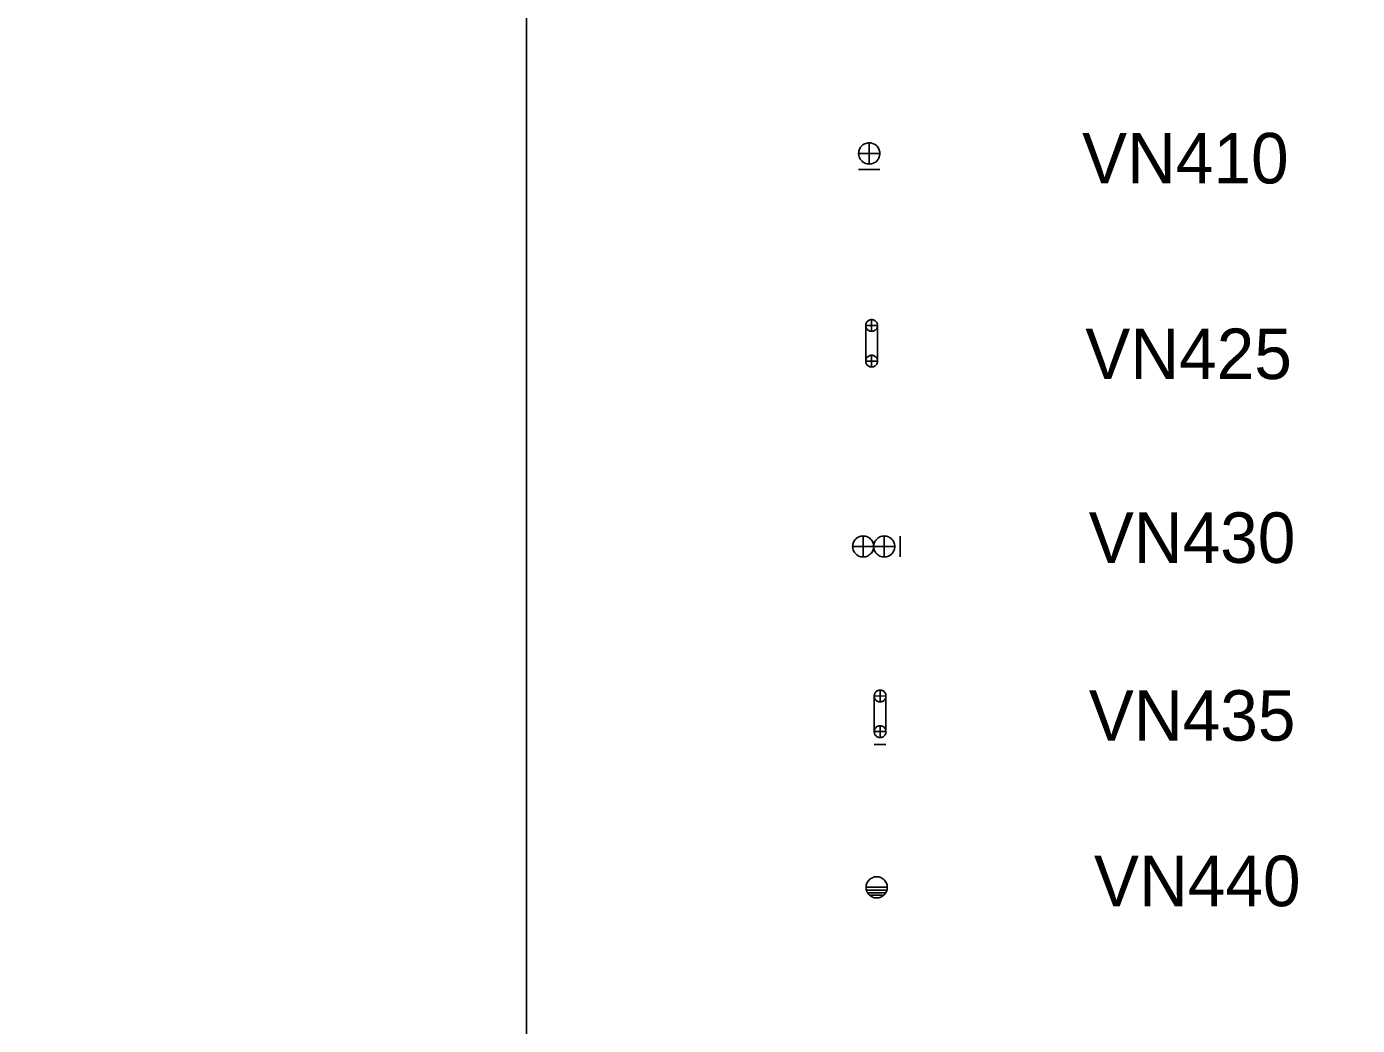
# Model space of a CAD drawing. Extents: x -592825 to -592404, y -1153473 to -1153230.
# Drawn here: x -592615.49 to -592575.99, y -1153381.85 to -1153352.19 of the extents above; entities that cross this region are included whole.
import ezdxf

# ---------------------------------------------------------------- set-up
doc = ezdxf.new("R2010")
doc.units = 0
doc.layers.add('Vrstva 45', color=7, linetype='Continuous')
doc.layers.add('Vrstva 63', color=7, linetype='Continuous')

msp = doc.modelspace()

# ---------------------------------------------------------------- linework, layer by layer
at = {"layer": 'Vrstva 45'}
for points in [[(-592590.165, -1153355.955), (-592590.167, -1153355.922), (-592590.171, -1153355.89), (-592590.18, -1153355.858), (-592590.192, -1153355.826), (-592590.207, -1153355.798), (-592590.225, -1153355.77), (-592590.245, -1153355.744), (-592590.269, -1153355.721), (-592590.295, -1153355.7), (-592590.323, -1153355.682), (-592590.351, -1153355.667), (-592590.383, -1153355.656), (-592590.415, -1153355.646), (-592590.447, -1153355.642), (-592590.48, -1153355.64), (-592590.513, -1153355.642), (-592590.545, -1153355.646), (-592590.577, -1153355.656), (-592590.608, -1153355.668), (-592590.637, -1153355.682), (-592590.665, -1153355.7), (-592590.691, -1153355.72), (-592590.714, -1153355.744), (-592590.735, -1153355.77), (-592590.753, -1153355.798), (-592590.767, -1153355.826), (-592590.779, -1153355.858), (-592590.788, -1153355.89), (-592590.793, -1153355.922), (-592590.795, -1153355.956), (-592590.793, -1153355.988), (-592590.788, -1153356.02), (-592590.78, -1153356.052), (-592590.767, -1153356.083), (-592590.753, -1153356.112), (-592590.735, -1153356.14), (-592590.714, -1153356.166), (-592590.691, -1153356.189), (-592590.665, -1153356.21), (-592590.637, -1153356.228), (-592590.608, -1153356.243), (-592590.577, -1153356.254), (-592590.545, -1153356.263), (-592590.513, -1153356.268), (-592590.48, -1153356.27), (-592590.447, -1153356.268), (-592590.415, -1153356.264), (-592590.383, -1153356.254), (-592590.351, -1153356.242), (-592590.323, -1153356.228), (-592590.295, -1153356.21), (-592590.269, -1153356.19), (-592590.245, -1153356.166), (-592590.225, -1153356.14), (-592590.207, -1153356.112), (-592590.192, -1153356.083), (-592590.18, -1153356.052), (-592590.171, -1153356.02), (-592590.167, -1153355.988), (-592590.165, -1153355.955)], [(-592590.481, -1153355.639), (-592590.481, -1153356.269)], [(-592590.797, -1153355.954), (-592590.166, -1153355.954)], [(-592590.796, -1153356.432), (-592590.166, -1153356.432)], [(-592590.235, -1153361.064), (-592590.235, -1153361.046), (-592590.238, -1153361.028), (-592590.243, -1153361.01), (-592590.249, -1153360.993), (-592590.257, -1153360.976), (-592590.267, -1153360.962), (-592590.279, -1153360.947), (-592590.292, -1153360.934), (-592590.306, -1153360.923), (-592590.321, -1153360.912), (-592590.337, -1153360.904), (-592590.355, -1153360.898), (-592590.373, -1153360.893), (-592590.391, -1153360.89), (-592590.409, -1153360.89), (-592590.427, -1153360.89), (-592590.445, -1153360.893), (-592590.463, -1153360.898), (-592590.479, -1153360.904), (-592590.496, -1153360.912), (-592590.511, -1153360.923), (-592590.525, -1153360.934), (-592590.538, -1153360.947), (-592590.549, -1153360.962), (-592590.56, -1153360.976), (-592590.568, -1153360.993), (-592590.575, -1153361.01), (-592590.579, -1153361.028), (-592590.582, -1153361.046), (-592590.583, -1153361.064), (-592590.582, -1153361.082), (-592590.579, -1153361.1), (-592590.575, -1153361.118), (-592590.568, -1153361.135), (-592590.56, -1153361.151), (-592590.55, -1153361.166), (-592590.539, -1153361.18), (-592590.525, -1153361.194), (-592590.511, -1153361.206), (-592590.496, -1153361.215), (-592590.479, -1153361.224), (-592590.463, -1153361.23), (-592590.445, -1153361.234), (-592590.427, -1153361.238), (-592590.409, -1153361.238), (-592590.391, -1153361.238), (-592590.373, -1153361.234), (-592590.355, -1153361.23), (-592590.337, -1153361.224), (-592590.321, -1153361.215), (-592590.306, -1153361.205), (-592590.292, -1153361.194), (-592590.279, -1153361.18), (-592590.267, -1153361.166), (-592590.257, -1153361.151), (-592590.249, -1153361.135), (-592590.243, -1153361.118), (-592590.238, -1153361.1), (-592590.235, -1153361.082), (-592590.235, -1153361.064)], [(-592590.235, -1153361.064), (-592590.583, -1153361.064)], [(-592590.583, -1153361.064), (-592590.583, -1153362.122)], [(-592590.409, -1153360.89), (-592590.409, -1153361.238)], [(-592590.235, -1153361.064), (-592590.234, -1153362.122)], [(-592590.234, -1153362.122), (-592590.235, -1153362.104), (-592590.238, -1153362.086), (-592590.243, -1153362.068), (-592590.249, -1153362.051), (-592590.257, -1153362.035), (-592590.267, -1153362.02), (-592590.279, -1153362.006), (-592590.292, -1153361.992), (-592590.306, -1153361.981), (-592590.321, -1153361.971), (-592590.337, -1153361.962), (-592590.355, -1153361.956), (-592590.373, -1153361.952), (-592590.391, -1153361.949), (-592590.409, -1153361.948), (-592590.427, -1153361.949), (-592590.445, -1153361.952), (-592590.463, -1153361.956), (-592590.48, -1153361.963), (-592590.496, -1153361.971), (-592590.511, -1153361.981), (-592590.525, -1153361.992), (-592590.539, -1153362.006), (-592590.549, -1153362.02), (-592590.56, -1153362.035), (-592590.568, -1153362.051), (-592590.575, -1153362.068), (-592590.579, -1153362.086), (-592590.582, -1153362.104), (-592590.583, -1153362.122), (-592590.582, -1153362.14), (-592590.579, -1153362.158), (-592590.575, -1153362.176), (-592590.568, -1153362.193), (-592590.56, -1153362.21), (-592590.55, -1153362.224), (-592590.538, -1153362.239), (-592590.525, -1153362.252), (-592590.511, -1153362.264), (-592590.496, -1153362.273), (-592590.48, -1153362.282), (-592590.463, -1153362.288), (-592590.445, -1153362.293), (-592590.427, -1153362.296), (-592590.409, -1153362.296), (-592590.391, -1153362.296), (-592590.373, -1153362.293), (-592590.355, -1153362.288), (-592590.337, -1153362.282), (-592590.321, -1153362.273), (-592590.306, -1153362.264), (-592590.291, -1153362.252), (-592590.279, -1153362.239), (-592590.267, -1153362.225), (-592590.257, -1153362.21), (-592590.249, -1153362.194), (-592590.243, -1153362.176), (-592590.238, -1153362.158), (-592590.235, -1153362.14), (-592590.234, -1153362.122)], [(-592590.234, -1153362.122), (-592590.583, -1153362.122)], [(-592590.409, -1153361.948), (-592590.409, -1153362.296)], [(-592590.347, -1153367.628), (-592590.349, -1153367.595), (-592590.354, -1153367.562), (-592590.363, -1153367.531), (-592590.375, -1153367.501), (-592590.389, -1153367.472), (-592590.407, -1153367.444), (-592590.428, -1153367.418), (-592590.451, -1153367.396), (-592590.476, -1153367.375), (-592590.503, -1153367.357), (-592590.533, -1153367.342), (-592590.563, -1153367.33), (-592590.595, -1153367.322), (-592590.627, -1153367.318), (-592590.659, -1153367.315), (-592590.693, -1153367.318), (-592590.725, -1153367.322), (-592590.757, -1153367.331), (-592590.787, -1153367.342), (-592590.816, -1153367.358), (-592590.843, -1153367.375), (-592590.869, -1153367.396), (-592590.892, -1153367.419), (-592590.913, -1153367.444), (-592590.93, -1153367.472), (-592590.945, -1153367.5), (-592590.957, -1153367.531), (-592590.965, -1153367.563), (-592590.971, -1153367.595), (-592590.973, -1153367.628), (-592590.971, -1153367.66), (-592590.965, -1153367.692), (-592590.957, -1153367.724), (-592590.945, -1153367.756), (-592590.93, -1153367.784), (-592590.913, -1153367.811), (-592590.892, -1153367.836), (-592590.869, -1153367.86), (-592590.843, -1153367.88), (-592590.815, -1153367.898), (-592590.787, -1153367.913), (-592590.757, -1153367.924), (-592590.725, -1153367.934), (-592590.693, -1153367.938), (-592590.659, -1153367.94), (-592590.627, -1153367.939), (-592590.595, -1153367.934), (-592590.563, -1153367.925), (-592590.533, -1153367.913), (-592590.503, -1153367.898), (-592590.477, -1153367.88), (-592590.451, -1153367.86), (-592590.428, -1153367.837), (-592590.407, -1153367.812), (-592590.389, -1153367.784), (-592590.374, -1153367.755), (-592590.363, -1153367.724), (-592590.354, -1153367.693), (-592590.349, -1153367.661), (-592590.347, -1153367.628)], [(-592590.657, -1153367.318), (-592590.657, -1153367.938)], [(-592589.722, -1153367.628), (-592589.724, -1153367.595), (-592589.729, -1153367.563), (-592589.738, -1153367.531), (-592589.749, -1153367.501), (-592589.764, -1153367.472), (-592589.782, -1153367.444), (-592589.803, -1153367.418), (-592589.825, -1153367.396), (-592589.851, -1153367.376), (-592589.879, -1153367.358), (-592589.908, -1153367.342), (-592589.938, -1153367.33), (-592589.97, -1153367.322), (-592590.002, -1153367.318), (-592590.035, -1153367.315), (-592590.067, -1153367.318), (-592590.099, -1153367.322), (-592590.131, -1153367.331), (-592590.163, -1153367.342), (-592590.191, -1153367.358), (-592590.218, -1153367.375), (-592590.243, -1153367.396), (-592590.267, -1153367.419), (-592590.287, -1153367.444), (-592590.305, -1153367.472), (-592590.321, -1153367.501), (-592590.331, -1153367.532), (-592590.341, -1153367.562), (-592590.345, -1153367.595), (-592590.347, -1153367.628), (-592590.346, -1153367.661), (-592590.341, -1153367.693), (-592590.331, -1153367.724), (-592590.32, -1153367.756), (-592590.305, -1153367.784), (-592590.288, -1153367.812), (-592590.267, -1153367.836), (-592590.244, -1153367.86), (-592590.218, -1153367.88), (-592590.191, -1153367.898), (-592590.161, -1153367.914), (-592590.131, -1153367.924), (-592590.1, -1153367.934), (-592590.067, -1153367.938), (-592590.035, -1153367.94), (-592590.002, -1153367.938), (-592589.969, -1153367.934), (-592589.938, -1153367.925), (-592589.908, -1153367.914), (-592589.879, -1153367.898), (-592589.851, -1153367.881), (-592589.825, -1153367.86), (-592589.803, -1153367.837), (-592589.782, -1153367.812), (-592589.765, -1153367.784), (-592589.749, -1153367.755), (-592589.737, -1153367.724), (-592589.729, -1153367.693), (-592589.724, -1153367.661), (-592589.722, -1153367.628)], [(-592590.037, -1153367.318), (-592590.037, -1153367.938)], [(-592589.565, -1153367.318), (-592589.565, -1153367.938)], [(-592590.973, -1153367.628), (-592589.722, -1153367.628)], [(-592589.983, -1153372.069), (-592589.983, -1153372.05), (-592589.987, -1153372.032), (-592589.991, -1153372.015), (-592589.997, -1153371.998), (-592590.006, -1153371.982), (-592590.016, -1153371.966), (-592590.027, -1153371.952), (-592590.041, -1153371.939), (-592590.055, -1153371.928), (-592590.07, -1153371.918), (-592590.086, -1153371.909), (-592590.103, -1153371.902), (-592590.121, -1153371.898), (-592590.139, -1153371.896), (-592590.157, -1153371.894), (-592590.175, -1153371.895), (-592590.193, -1153371.898), (-592590.211, -1153371.903), (-592590.228, -1153371.91), (-592590.245, -1153371.918), (-592590.26, -1153371.928), (-592590.274, -1153371.939), (-592590.287, -1153371.952), (-592590.299, -1153371.966), (-592590.308, -1153371.982), (-592590.317, -1153371.998), (-592590.323, -1153372.015), (-592590.328, -1153372.032), (-592590.331, -1153372.05), (-592590.331, -1153372.068), (-592590.331, -1153372.087), (-592590.328, -1153372.105), (-592590.323, -1153372.123), (-592590.317, -1153372.14), (-592590.309, -1153372.156), (-592590.298, -1153372.171), (-592590.287, -1153372.186), (-592590.274, -1153372.198), (-592590.26, -1153372.21), (-592590.245, -1153372.22), (-592590.228, -1153372.228), (-592590.211, -1153372.234), (-592590.193, -1153372.24), (-592590.175, -1153372.242), (-592590.157, -1153372.243), (-592590.139, -1153372.242), (-592590.121, -1153372.24), (-592590.103, -1153372.234), (-592590.086, -1153372.228), (-592590.07, -1153372.22), (-592590.055, -1153372.21), (-592590.041, -1153372.198), (-592590.027, -1153372.186), (-592590.016, -1153372.171), (-592590.006, -1153372.156), (-592589.997, -1153372.14), (-592589.991, -1153372.122), (-592589.987, -1153372.105), (-592589.983, -1153372.087), (-592589.983, -1153372.069)], [(-592589.983, -1153372.069), (-592590.331, -1153372.068)], [(-592590.331, -1153372.068), (-592590.331, -1153373.127)], [(-592590.157, -1153371.894), (-592590.157, -1153372.243)], [(-592589.983, -1153372.069), (-592589.983, -1153373.127)], [(-592589.983, -1153373.127), (-592589.983, -1153373.108), (-592589.987, -1153373.091), (-592589.991, -1153373.074), (-592589.997, -1153373.056), (-592590.006, -1153373.04), (-592590.016, -1153373.024), (-592590.027, -1153373.01), (-592590.041, -1153372.997), (-592590.055, -1153372.986), (-592590.069, -1153372.976), (-592590.086, -1153372.968), (-592590.103, -1153372.961), (-592590.121, -1153372.956), (-592590.139, -1153372.954), (-592590.157, -1153372.952), (-592590.175, -1153372.954), (-592590.193, -1153372.956), (-592590.211, -1153372.961), (-592590.228, -1153372.968), (-592590.245, -1153372.976), (-592590.26, -1153372.986), (-592590.274, -1153372.997), (-592590.287, -1153373.01), (-592590.299, -1153373.024), (-592590.309, -1153373.04), (-592590.317, -1153373.056), (-592590.323, -1153373.074), (-592590.327, -1153373.09), (-592590.331, -1153373.108), (-592590.331, -1153373.127), (-592590.331, -1153373.145), (-592590.328, -1153373.164), (-592590.323, -1153373.181), (-592590.317, -1153373.198), (-592590.309, -1153373.214), (-592590.299, -1153373.23), (-592590.287, -1153373.244), (-592590.274, -1153373.256), (-592590.26, -1153373.268), (-592590.245, -1153373.278), (-592590.228, -1153373.286), (-592590.211, -1153373.293), (-592590.193, -1153373.298), (-592590.175, -1153373.3), (-592590.157, -1153373.302), (-592590.139, -1153373.3), (-592590.121, -1153373.298), (-592590.103, -1153373.293), (-592590.086, -1153373.286), (-592590.069, -1153373.278), (-592590.055, -1153373.268), (-592590.041, -1153373.256), (-592590.027, -1153373.244), (-592590.016, -1153373.23), (-592590.006, -1153373.214), (-592589.997, -1153373.198), (-592589.991, -1153373.181), (-592589.987, -1153373.163), (-592589.983, -1153373.145), (-592589.983, -1153373.127)], [(-592589.983, -1153373.127), (-592590.331, -1153373.127)], [(-592590.157, -1153372.952), (-592590.157, -1153373.302)], [(-592590.338, -1153373.504), (-592589.983, -1153373.504)], [(-592589.945, -1153377.751), (-592589.946, -1153377.718), (-592589.951, -1153377.686), (-592589.959, -1153377.654), (-592589.971, -1153377.623), (-592589.987, -1153377.593), (-592590.005, -1153377.566), (-592590.025, -1153377.54), (-592590.049, -1153377.517), (-592590.074, -1153377.496), (-592590.101, -1153377.478), (-592590.131, -1153377.463), (-592590.162, -1153377.451), (-592590.193, -1153377.442), (-592590.226, -1153377.438), (-592590.259, -1153377.436), (-592590.292, -1153377.438), (-592590.325, -1153377.443), (-592590.357, -1153377.451), (-592590.387, -1153377.464), (-592590.417, -1153377.478), (-592590.445, -1153377.496), (-592590.47, -1153377.517), (-592590.493, -1153377.54), (-592590.514, -1153377.566), (-592590.532, -1153377.593), (-592590.547, -1153377.622), (-592590.559, -1153377.654), (-592590.568, -1153377.685), (-592590.573, -1153377.718), (-592590.574, -1153377.751), (-592590.573, -1153377.784), (-592590.567, -1153377.816), (-592590.559, -1153377.848), (-592590.547, -1153377.88), (-592590.532, -1153377.908), (-592590.514, -1153377.936), (-592590.494, -1153377.962), (-592590.47, -1153377.985), (-592590.445, -1153378.006), (-592590.417, -1153378.024), (-592590.387, -1153378.038), (-592590.357, -1153378.05), (-592590.325, -1153378.059), (-592590.292, -1153378.064), (-592590.259, -1153378.066), (-592590.226, -1153378.064), (-592590.194, -1153378.059), (-592590.162, -1153378.05), (-592590.131, -1153378.038), (-592590.102, -1153378.024), (-592590.074, -1153378.006), (-592590.049, -1153377.984), (-592590.025, -1153377.962), (-592590.005, -1153377.936), (-592589.987, -1153377.908), (-592589.971, -1153377.879), (-592589.959, -1153377.848), (-592589.951, -1153377.816), (-592589.946, -1153377.784), (-592589.945, -1153377.751)], [(-592590.575, -1153377.748), (-592589.945, -1153377.749)], [(-592590.561, -1153377.838), (-592589.975, -1153377.837)], [(-592590.516, -1153377.912), (-592590.009, -1153377.911)], [(-592590.447, -1153377.986), (-592590.083, -1153377.986)]]:
    msp.add_lwpolyline(points, dxfattribs=at)
at = {"layer": 'Vrstva 63'}
for points in [[(-592679.084, -1153338.599), (-592600.649, -1153338.599), (-592600.649, -1153436.347), (-592679.084, -1153436.347)], [(-592600.649, -1153338.599), (-592513.86, -1153338.599), (-592513.86, -1153436.347), (-592600.649, -1153436.347)]]:
    msp.add_lwpolyline(points, close=True, dxfattribs=at)

# ---------------------------------------------------------------- texts
for s, p in [('VN410', (-592584.163, -1153356.846)), ('VN425', (-592584.067, -1153362.656)), ('VN430', (-592583.963, -1153368.116)), ('VN435', (-592583.961, -1153373.396)), ('VN440', (-592583.809, -1153378.31))]:
    msp.add_text(s, height=1.5, dxfattribs=at).set_placement(p)

doc.saveas('drawing.dxf')
